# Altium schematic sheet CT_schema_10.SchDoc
size 391 x 278 mm
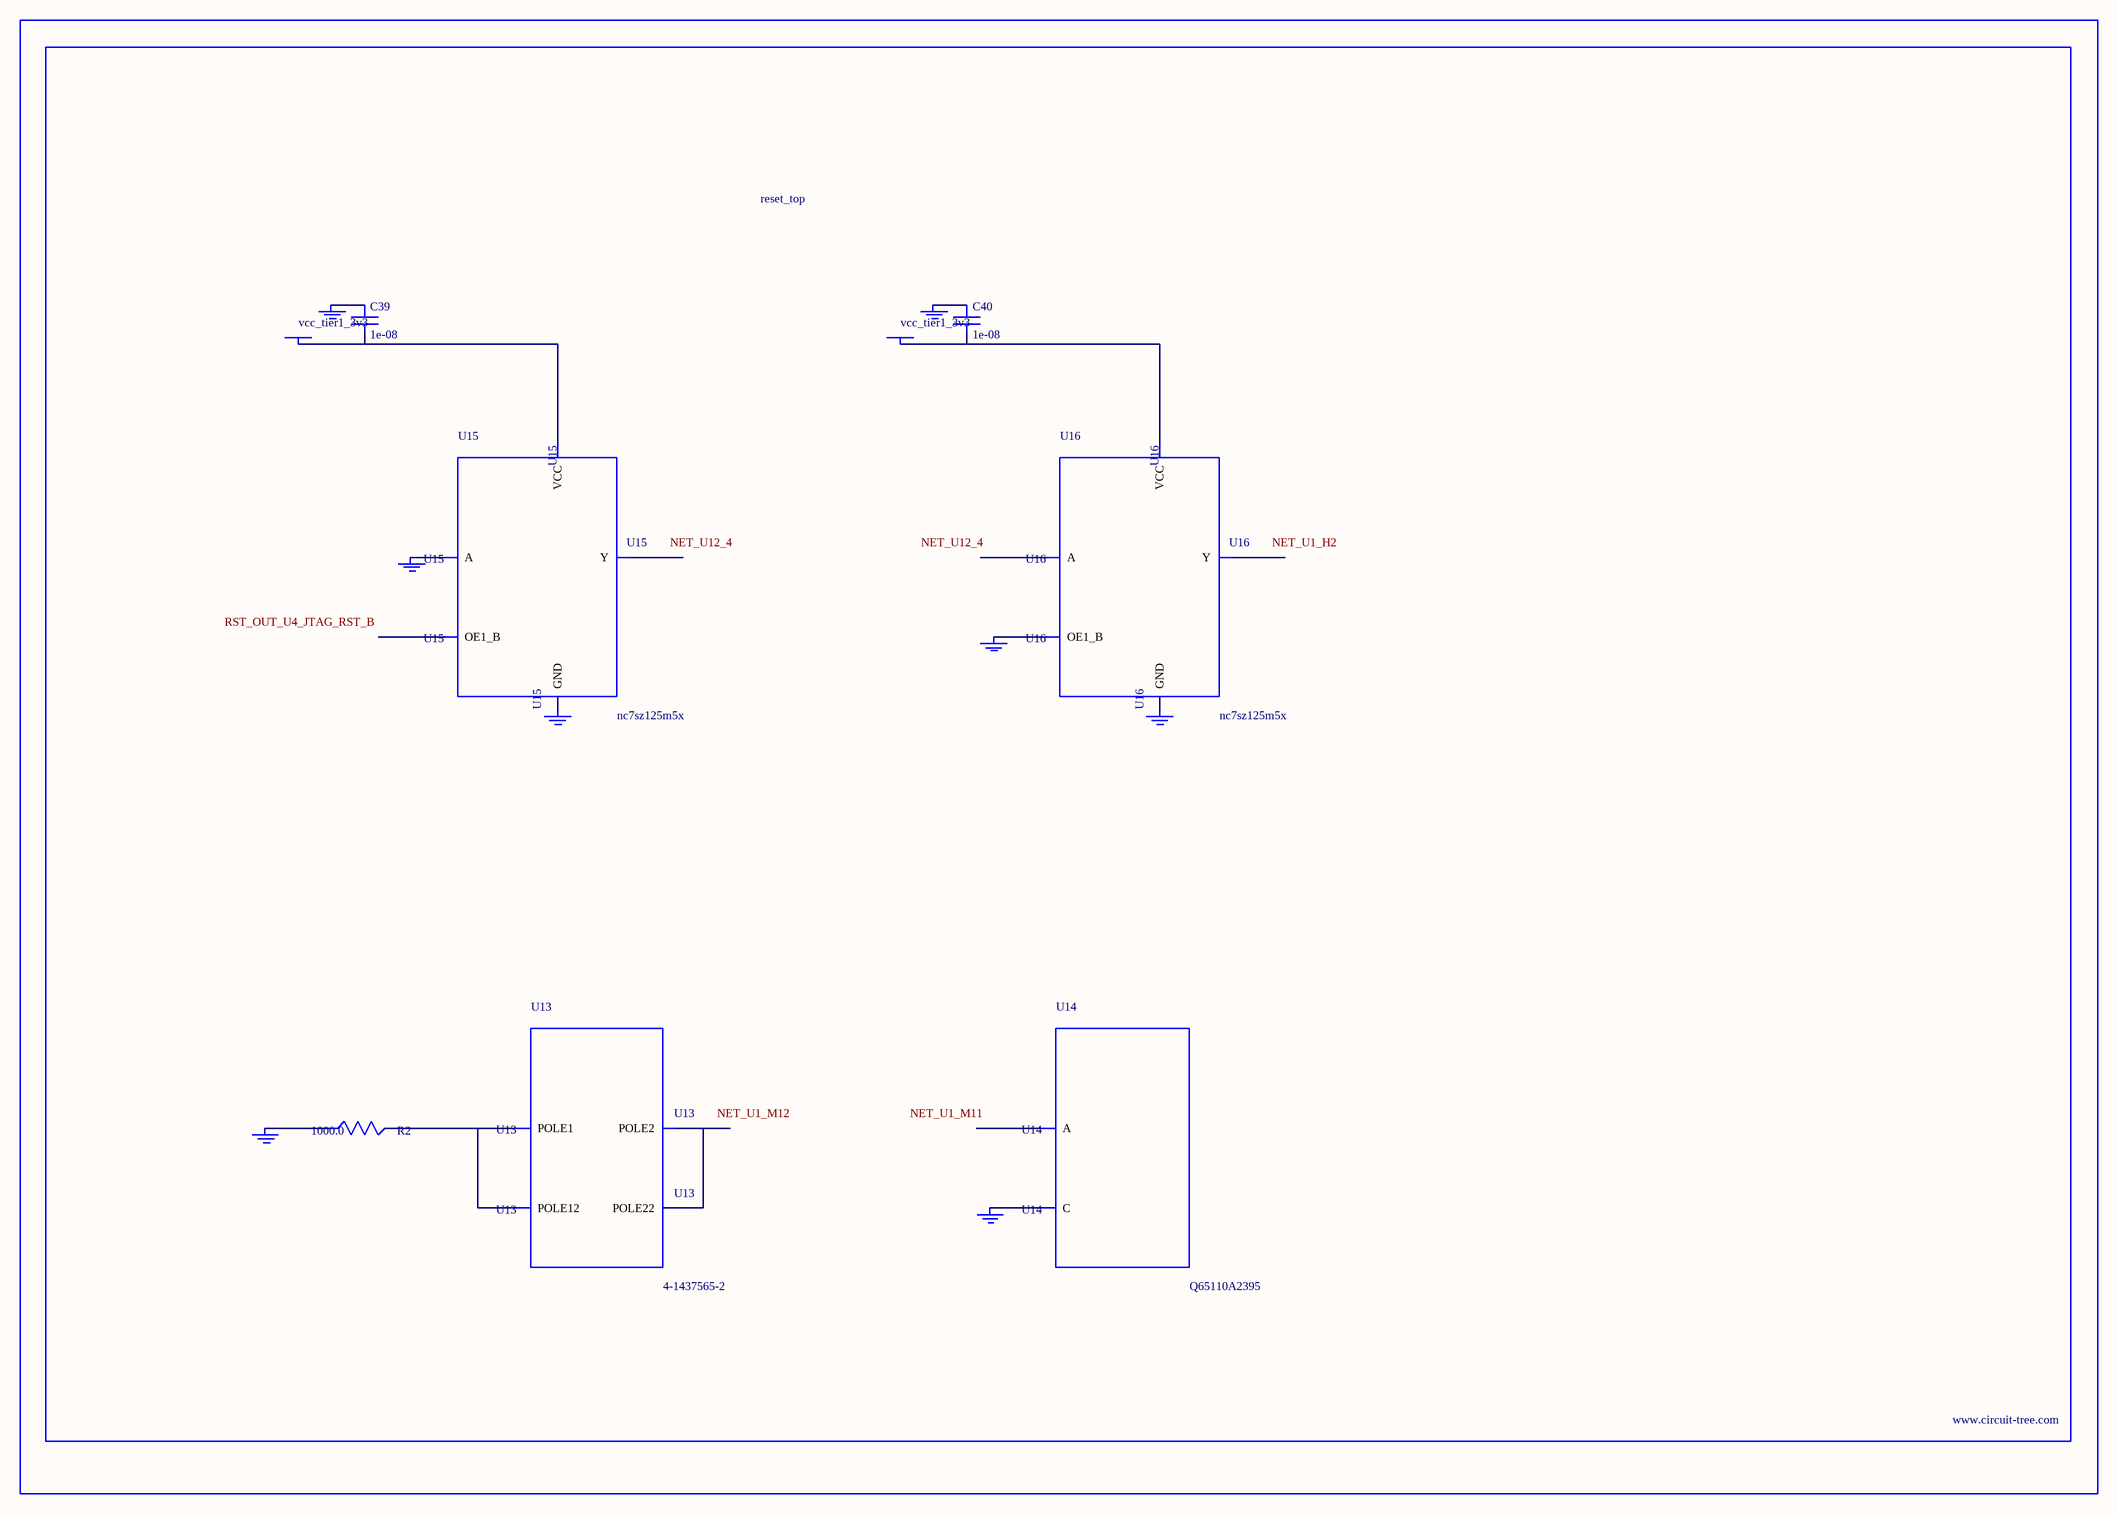
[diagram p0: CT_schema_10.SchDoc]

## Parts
BORDER9  (no value)
C39  1e-08  [C0402]
C40  1e-08  [C0402]
GND_INSTANCE_9_0  (no value)
GND_INSTANCE_9_1  (no value)
GND_INSTANCE_9_2  (no value)
GND_INSTANCE_9_3  (no value)
GND_INSTANCE_9_4  (no value)
GND_INSTANCE_9_5  (no value)
GND_INSTANCE_9_6  (no value)
GND_INSTANCE_9_7  (no value)
POWER_INSTANCE_9_0  vcc_tier1_3v3
POWER_INSTANCE_9_1  vcc_tier1_3v3
R2  1000.0  [R0603]
U13  4-1437565-2  [SW_4-1437565-2]
U14  Q65110A2395  [LGM67K-G1J2-24-Z]
U15  nc7sz125m5x  [NC7SZ125M5X]
U16  nc7sz125m5x  [NC7SZ125M5X]

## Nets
NetC39_1: C39.1 GND_INSTANCE_9_2.0(GND)
NetC39_2: C39.2 POWER_INSTANCE_9_0.0(PWR) U15.5(VCC)
NetC40_1: C40.1 GND_INSTANCE_9_5.0(GND)
NetC40_2: C40.2 POWER_INSTANCE_9_1.0(PWR) U16.5(VCC)
NetGND_INSTANCE_9_0_0: GND_INSTANCE_9_0.0(GND) R2.1
NetGND_INSTANCE_9_1_0: GND_INSTANCE_9_1.0(GND) U14.C
NetGND_INSTANCE_9_3_0: GND_INSTANCE_9_3.0(GND) U15.2(A)
NetGND_INSTANCE_9_4_0: GND_INSTANCE_9_4.0(GND) U15.3(GND)
NetGND_INSTANCE_9_6_0: GND_INSTANCE_9_6.0(GND) U16.1(OE1_B)
NetGND_INSTANCE_9_7_0: GND_INSTANCE_9_7.0(GND) U16.3(GND)
NetR2_2: R2.2 U13.1(POLE1) U13.2(POLE12)
NetU13_3: U13.3(POLE2) U13.4(POLE22)

Not connected (* = marked no-connect by the designer): U14 A; U15 1(OE1_B) 4(Y); U16 2(A) 4(Y)

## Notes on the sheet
- Labels drawn without touching a wire or pin: NET_U1_H2, NET_U1_M11, NET_U1_M12, NET_U12_4, RST_OUT_U4_JTAG_RST_B

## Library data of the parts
BORDER9 = BORDER_PAGE9
C39 C40 = C0402C103K3RAC
GND_INSTANCE_9_0-GND_INSTANCE_9_7 = GND
POWER_INSTANCE_9_0 POWER_INSTANCE_9_1 = PWR
R2 = RC0603JR-071KL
